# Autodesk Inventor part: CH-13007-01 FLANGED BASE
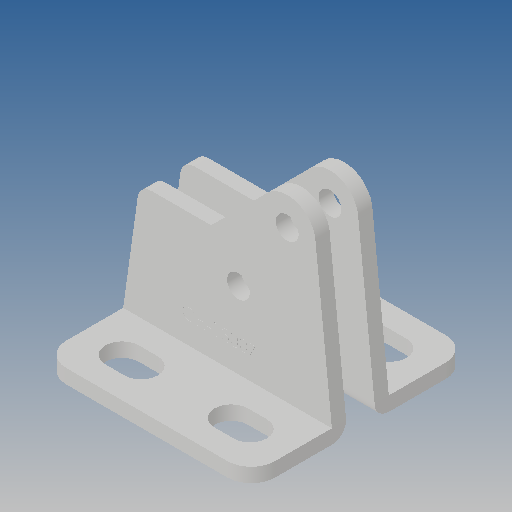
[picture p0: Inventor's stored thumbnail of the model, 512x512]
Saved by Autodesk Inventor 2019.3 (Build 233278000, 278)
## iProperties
Created: 2012-09
Part Number: CH-13007-01 FLANGED BASE
Material: Ogólny
Document SubType Name: Modeling
Designer: CADENGINEERING4
Density: 1 g/cm^3
Appearance: Domyślna
Author: CADENGINEERING4
Revision Number: ÈÎºÎ
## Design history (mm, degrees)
feature "ÇÐ³ý-À­Éì2"
feature "ÇÐ³ý-À­Éì5"
node "Bryła1"
node "Bryła2"
